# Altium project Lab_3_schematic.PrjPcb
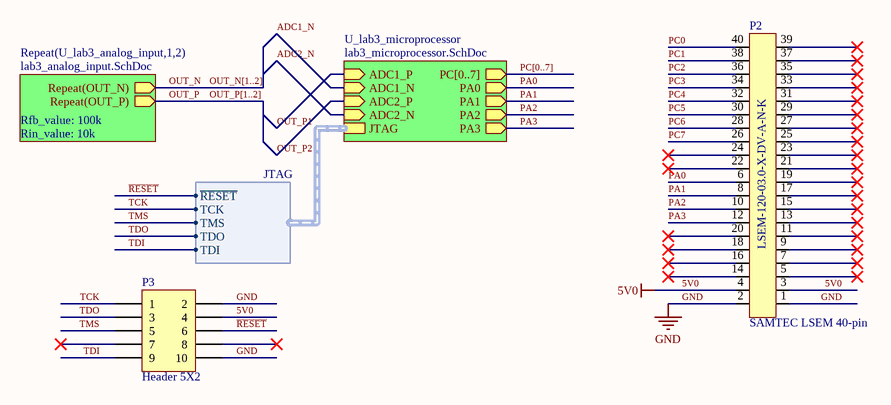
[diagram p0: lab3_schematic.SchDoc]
3 sheets, 24 parts. Net scope: hierarchical (ports join the sheet entries above them; power ports are global).
Board file: PCB2.PcbDoc
Sheets:
  lab3_schematic.SchDoc
    U_lab3_analog_input1 = lab3_analog_input.SchDoc
    U_lab3_analog_input2 = lab3_analog_input.SchDoc
    U_lab3_microprocessor = lab3_microprocessor.SchDoc

## Sheet lab3_schematic.SchDoc
size A4; Author: Michał Wojna; CompanyName: AGH; Revision: 1; SheetNumber: 1; SheetTotal: 3; SPICEModelCacheRHFFZEVK: <root> / <DocumentId>RHFFZEVK</DocumentId> / </root>

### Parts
P2  SAMTEC LSEM 40-pin  [LSEM-120-03.0-L-DV-A-N-K-TR]
P3  Header 5X2  [HDR2X5]

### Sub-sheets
Repeat(U_lab3_analog_input,1,2) = lab3_analog_input.SchDoc: Repeat(OUT_P) (out), Repeat(OUT_N) (out)  | Rfb_value: 100k; Rin_value: 10k
U_lab3_microprocessor = lab3_microprocessor.SchDoc: PC[0..7] (out), PA0 (out), PA1 (out), PA2 (out), PA3 (out), JTAG (harness JTAG), ADC2_P (in), ADC2_N (in), ADC1_N (in), ADC1_P (in)

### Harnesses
JTAG: ~{RESET}, TCK, TMS, TDO, TDI

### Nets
5V0: P2.3 P2.4 P3.4
GND: P2.1 P2.2 P3.2 P3.10
~{RESET}: P3.6 ; sheet U_lab3_microprocessor/JTAG.~{RESET}
PA0: P2.6 ; sheet U_lab3_microprocessor/PA0
PA1: P2.8 ; sheet U_lab3_microprocessor/PA1
PA2: P2.10 ; sheet U_lab3_microprocessor/PA2
PA3: P2.12 ; sheet U_lab3_microprocessor/PA3
PC0: P2.40
PC1: P2.38
PC2: P2.36
PC3: P2.34
PC4: P2.32
PC5: P2.30
PC6: P2.28
PC7: P2.26
TCK: P3.1 ; sheet U_lab3_microprocessor/JTAG.TCK
TDI: P3.9 ; sheet U_lab3_microprocessor/JTAG.TDI
TDO: P3.3 ; sheet U_lab3_microprocessor/JTAG.TDO
TMS: P3.5 ; sheet U_lab3_microprocessor/JTAG.TMS

Not connected (* = marked no-connect by the designer): P2 5(3)* 7(4)* 9(5)* 11(6)* 13(7)* 14(8)* 15(8)* 16(9)* 17(9)* 18(10)* 19(10)* 20(11)* 21(11)* 22(12)* 23(12)* 24(13)* 25(13)* 27(14)* 29(15)* 31(16)* 33(17)* 35(18)* 37(19)* 39(20)*; P3 7* 8*

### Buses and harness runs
bus OUT_N[1..2]
bus OUT_P[1..2]
bus PC[0..7] = sheet U_lab3_microprocessor/PC[0..7]

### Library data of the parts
P2 = LSEM-120-03.0-X-DV-A-N-K
P3 = Header 5X2: Header, 5-Pin, Dual row

## Sheet lab3_analog_input.SchDoc
size A4; Author: Michał Wojna; CompanyName: AGH; Revision: 1; SheetNumber: 2; SheetTotal: 3
Used 2 times, as channels U_lab3_analog_input1, U_lab3_analog_input2. Parts and nets are listed once, with the designators drawn on the sheet.
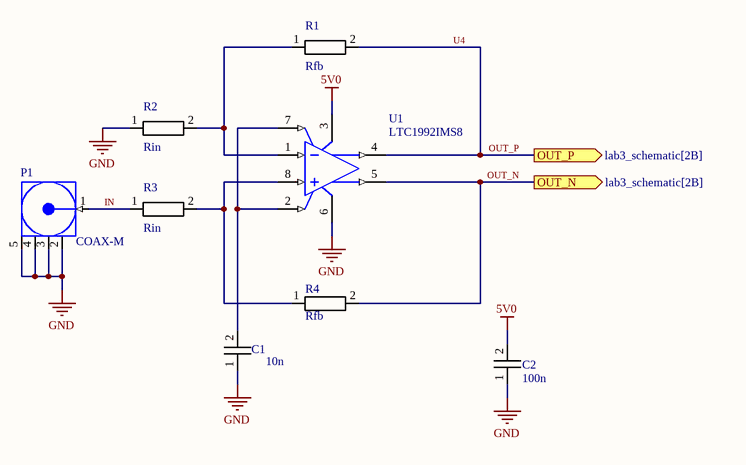
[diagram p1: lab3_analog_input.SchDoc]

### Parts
C1  10n  [0805_STD]
C2  100n  [0805_STD]
P1  COAX-M  [MMCX2.54-V5]
R1  Rfb  [0603]
R2  Rin  [0603]
R3  Rin  [0603]
R4  Rfb  [0603]
U1  LTC1992IMS8  [LT-MS8-8_L]

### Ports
OUT_N (out, see lab3_schematic[2B]), OUT_P (out, see lab3_schematic[2B])

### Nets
5V0: C2.2(PIN) U1.3(+VS)
GND: C1.1(PIN) C2.1(PIN) P1.2(GND) P1.3(GND) P1.4(GND) P1.5(GND) R2.1(PIN) U1.6(-VS)
IN: P1.1(Signal) R3.1(PIN)
OUT_N: R4.2(PIN) U1.5(-OUT) ; port OUT_N
OUT_P: R1.2(PIN) U1.4(+OUT) ; port OUT_P  [also labelled U4]
NetC1_2: C1.2(PIN) U1.2(VOCM) U1.7(VMID)
NetR1_1: R1.1(PIN) R2.2(PIN) U1.1(-IN)
NetR3_2: R3.2(PIN) R4.1(PIN) U1.8(+IN)

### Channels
U_lab3_analog_input1: designators end in _U_lab3_analog_input1; ports OUT_N=OUT_N_U_lab3_analog_input1 OUT_P=ADC1_P
U_lab3_analog_input2: designators end in _U_lab3_analog_input2; ports OUT_N=OUT_N_U_lab3_analog_input2 OUT_P=ADC2_P

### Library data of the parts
C1 C2 = Capacitor
P1 = COAX-M: RF Coaxial PCB Connector, MMCX; Thru-Hole, Vertical Mount Plug,  50 Ohm Impedance; PackageDocument: Rev. A, 16-Jun-1997; PCB_Layout: Complies with manufacturer's recommendation.; DrillSize: Corresponds to nominal value.
R1-R4 = Resistor
U1 = CMP-0359-00506-2: Single Channel, Low Power, Fully Differential Input / Output Amplifier / Driver, 4 MHz Typical GBW, 0.75 V/us Typical SR, 2.4 to 12 V, 8-Pin SOP (MS8-8), Industrial; Manufacturer: Linear Technology; Is (mA) Typical: 0.65; Vs Min (V): 2.4; SR (V/us) Typical: 0.75; Vos (mV) Typical: 0.25; Vs Max (V): 12; Channels (#): 1; GBW (MHz) Typical: 4

## Sheet lab3_microprocessor.SchDoc
size A4; Author: Michał Wojna; CompanyName: AGH; Revision: 1; SheetNumber: 3; SheetTotal: 2
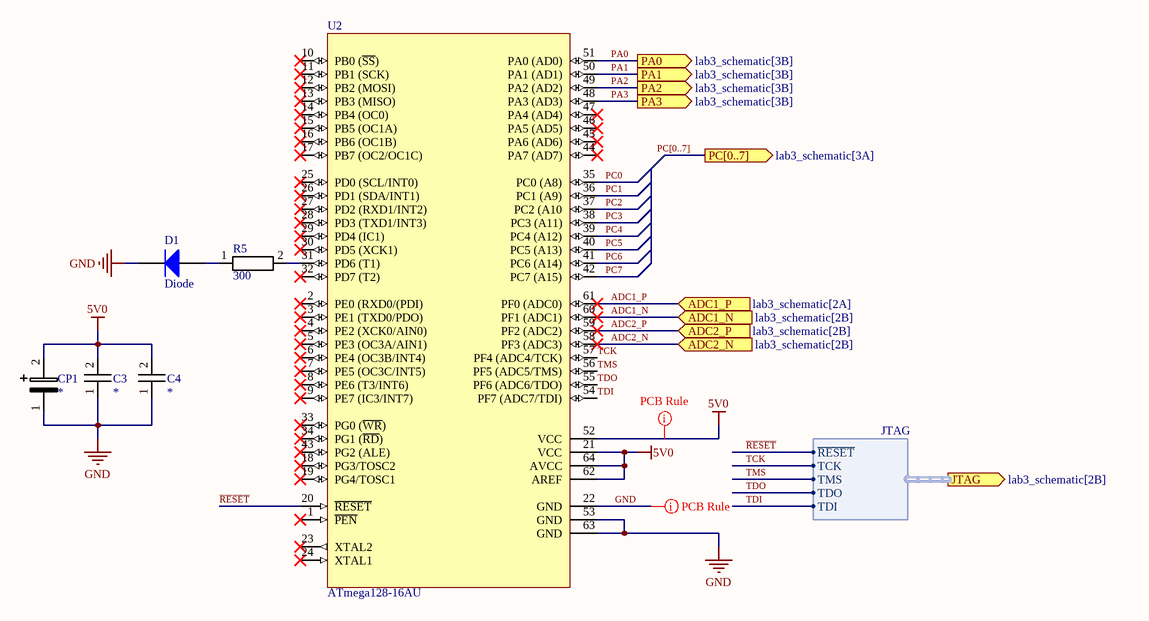
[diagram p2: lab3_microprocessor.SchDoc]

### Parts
C3  *  [0805_STD]
C4  *  [0805_STD]
CP1  *  [VJ_Tantalum_D]
D1  Diode  [SMC]
R5  300  [0603]
U2  ATmega128-16AU  [64A_M]

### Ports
ADC1_N (in, see lab3_schematic[2B]), ADC1_P (in, see lab3_schematic[2A]), ADC2_N (in, see lab3_schematic[2B]), ADC2_P (in, see lab3_schematic[2B]), JTAG (out, harness JTAG, see lab3_schematic[2B]), PA0 (out, see lab3_schematic[3B]), PA1 (out, see lab3_schematic[3B]), PA2 (out, see lab3_schematic[3B]), PA3 (out, see lab3_schematic[3B]), PC[0..7] (out, see lab3_schematic[3A])

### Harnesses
JTAG: ~{RESET}, TCK, TMS, TDO, TDI

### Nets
5V0: C3.2(PIN) C4.2(PIN) CP1.2(PIN) U2.21(VCC) U2.52(VCC) U2.62(AREF) U2.64(AVCC)
GND: C3.1(PIN) C4.1(PIN) CP1.1(PIN) D1.2(K) U2.22(GND) U2.53(GND) U2.63(GND)
~{RESET}: U2.20(~{RESET}) ; port JTAG.~{RESET}
ADC1_N: U2.60(PF1_(ADC1)) ; port ADC1_N
ADC1_P: U2.61(PF0_(ADC0)) ; port ADC1_P
ADC2_N: U2.58(PF3_(ADC3)) ; port ADC2_N
ADC2_P: U2.59(PF2_(ADC2)) ; port ADC2_P
PA0: U2.51(PA0_(AD0)) ; port PA0
PA1: U2.50(PA1_(AD1)) ; port PA1
PA2: U2.49(PA2_(AD2)) ; port PA2
PA3: U2.48(PA3_(AD3)) ; port PA3
PC0: U2.35(PC0_(A8))
PC1: U2.36(PC1_(A9))
PC2: U2.37(PC2_(A10)
PC3: U2.38(PC3_(A11))
PC4: U2.39(PC4_(A12))
PC5: U2.40(PC5_(A13))
PC6: U2.41(PC6_(A14))
PC7: U2.42(PC7_(A15))
TCK: U2.57(PF4_(ADC4/TCK)) ; port JTAG.TCK
TDI: U2.54(PF7_(ADC7/TDI)) ; port JTAG.TDI
TDO: U2.55(PF6_(ADC6/TDO)) ; port JTAG.TDO
TMS: U2.56(PF5_(ADC5/TMS)) ; port JTAG.TMS
NetD1_1: D1.1(A) R5.1(PIN)
NetR5_2: R5.2(PIN) U2.31(PD6_(T1))

Not connected (* = marked no-connect by the designer): U2 1(~{PEN})* 2(PE0_(RXD0/(PDI))* 3(PE1_(TXD0/PDO))* 4(PE2_(XCK0/AIN0))* 5(PE3_(OC3A/AIN1))* 6(PE4_(OC3B/INT4))* 7(PE5_(OC3C/INT5))* 8(PE6_(T3/INT6))* 9(PE7_(IC3/INT7))* 10(PB0_(~{SS}))* 11(PB1_(SCK))* 12(PB2_(MOSI))* 13(PB3_(MISO))* 14(PB4_(OC0))* 15(PB5_(OC1A))* 16(PB6_(OC1B))* 17(PB7_(OC2/OC1C))* 18(PG3/TOSC2)* 19(PG4/TOSC1)* 23(XTAL2)* 24(XTAL1)* 25(PD0_(SCL/INT0))* 26(PD1_(SDA/INT1))* 27(PD2_(RXD1/INT2))* 28(PD3_(TXD1/INT3))* 29(PD4_(IC1))* 30(PD5_(XCK1))* 32(PD7_(T2))* 33(PG0_(~{WR}))* 34(PG1_(~{RD}))* 43(PG2_(ALE))* 44(PA7_(AD7))* 45(PA6_(AD6))* 46(PA5_(AD5))* 47(PA4_(AD4))*

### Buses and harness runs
bus PC[0..7] = port PC[0..7]

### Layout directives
rule Width Constraint [Pref Width = 20mil    Min Width = 15mil    Max Width = 50mil]: 5V0, GND

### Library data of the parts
C3 C4 = Capacitor
CP1 = Capacitor_polarized
D1 = Diode: Default Diode
R5 = Resistor
U2 = CMP-0095-00259-2: 8-bit AVR Microcontroller, 4.5-5.5V, 128KB Flash, 4KB EEPROM, 4KB SRAM, 64-pin TQFP, Industrial Grade (-40°C to 85°C)

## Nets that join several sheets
5V0: lab3_schematic (P2.3 P2.4 P3.4), U_lab3_analog_input1 (C2_U_lab3_analog_input1.2 U1_U_lab3_analog_input1.3), U_lab3_analog_input2 (C2_U_lab3_analog_input2.2 U1_U_lab3_analog_input2.3), lab3_microprocessor (7 pins)
GND: lab3_schematic (P2.1 P2.2 P3.2 P3.10), U_lab3_analog_input1 (8 pins), U_lab3_analog_input2 (8 pins), lab3_microprocessor (7 pins)
~{RESET}: lab3_schematic (P3.6), lab3_microprocessor (U2.20)
ADC1_P: U_lab3_analog_input1 (R1_U_lab3_analog_input1.2 U1_U_lab3_analog_input1.4), lab3_microprocessor (U2.61)
ADC2_P: U_lab3_analog_input2 (R1_U_lab3_analog_input2.2 U1_U_lab3_analog_input2.4), lab3_microprocessor (U2.59)
PA0: lab3_schematic (P2.6), lab3_microprocessor (U2.51)
PA1: lab3_schematic (P2.8), lab3_microprocessor (U2.50)
PA2: lab3_schematic (P2.10), lab3_microprocessor (U2.49)
PA3: lab3_schematic (P2.12), lab3_microprocessor (U2.48)
PC0: lab3_schematic (P2.40), lab3_microprocessor (U2.35)
PC1: lab3_schematic (P2.38), lab3_microprocessor (U2.36)
PC2: lab3_schematic (P2.36), lab3_microprocessor (U2.37)
PC3: lab3_schematic (P2.34), lab3_microprocessor (U2.38)
PC4: lab3_schematic (P2.32), lab3_microprocessor (U2.39)
PC5: lab3_schematic (P2.30), lab3_microprocessor (U2.40)
PC6: lab3_schematic (P2.28), lab3_microprocessor (U2.41)
PC7: lab3_schematic (P2.26), lab3_microprocessor (U2.42)
TCK: lab3_schematic (P3.1), lab3_microprocessor (U2.57)
TDI: lab3_schematic (P3.9), lab3_microprocessor (U2.54)
TDO: lab3_schematic (P3.3), lab3_microprocessor (U2.55)
TMS: lab3_schematic (P3.5), lab3_microprocessor (U2.56)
